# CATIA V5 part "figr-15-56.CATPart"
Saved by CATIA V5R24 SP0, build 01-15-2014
Part number: Part1
Bounding box of the stored display mesh (mm): x -75 to -29.087, y -20 to 20, z 0 to 62.461
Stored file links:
  D:\KAVITA\CATIA V5-6R2014 Project_ Kavita\CATIA V5-6R2014_partfiles\Partfiles\c15_catia_v5-6r2014_prt\figr-15-56.CATPart
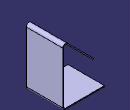
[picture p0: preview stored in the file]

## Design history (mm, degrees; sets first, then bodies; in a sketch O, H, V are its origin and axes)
SheetMetalParameters1: Thickness 1, BendRadius 2, KFactor 0.400515 {= log(min(100,max(20*SheetMetalParameters1.BendRadius,SheetMetalParameters1.Thickness)/SheetMetalParameters1.Thickness))/log(100)/2}, ReliefRadialLength 1, ReliefAxialLength 2, MinimumBendRadius 0
Body1 (main body)
  Sketch1 on xy-plane, origin (0, 0, 0), H (1, 0, 0), V (0, 1, 0)
    line L1 (-75, 20) -> (75, 20)
    line L2 (75, 20) -> (75, -20)
    line L3 (75, -20) -> (-75, -20)
    line L4 (-75, -20) -> (-75, 20)
    distance L1 L3 = 40
    distance L2 L4 = 150
    distance V L2 = 75
    distance H L3 = 20
    horizontal: L1 H, L3 H
    vertical: L2 V, L4 V
  Wall1: Thickness 1, Profile Sketch1
  Sketch2 on face of Wall1, origin (0, 0, 1), H (1, 0, 0), V (0, 1, 0)
    line L1 (-30.2021, 19.5432) -> (-30.2021, -20.6466)
    line L2 (31.0296, 19.5432) -> (31.0296, -20.6466)
    vertical: L1 V, L2 V
  FlatBend1: FlatBendAngle 90, FlatBendAngle 45, Axis Sketch2, FixedPoint vertex [face of Wall1 | face of Wall1 | face of Wall1], FlatBendKFactor 0.400515 {= log(min(100,max(20*FlatBend1.FlatBendRadius,SheetMetalParameters1.Thickness)/SheetMetalParameters1.Thickness))/log(100)/2}, FlatBendKFactor 0.400515 {= log(min(100,max(20*FlatBend1.FlatBendRadius,SheetMetalParameters1.Thickness)/SheetMetalParameters1.Thickness))/log(100)/2}, FlatBendRadius 2 {= SheetMetalParameters1.BendRadius}, FlatBendRadius 2 {= SheetMetalParameters1.BendRadius}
